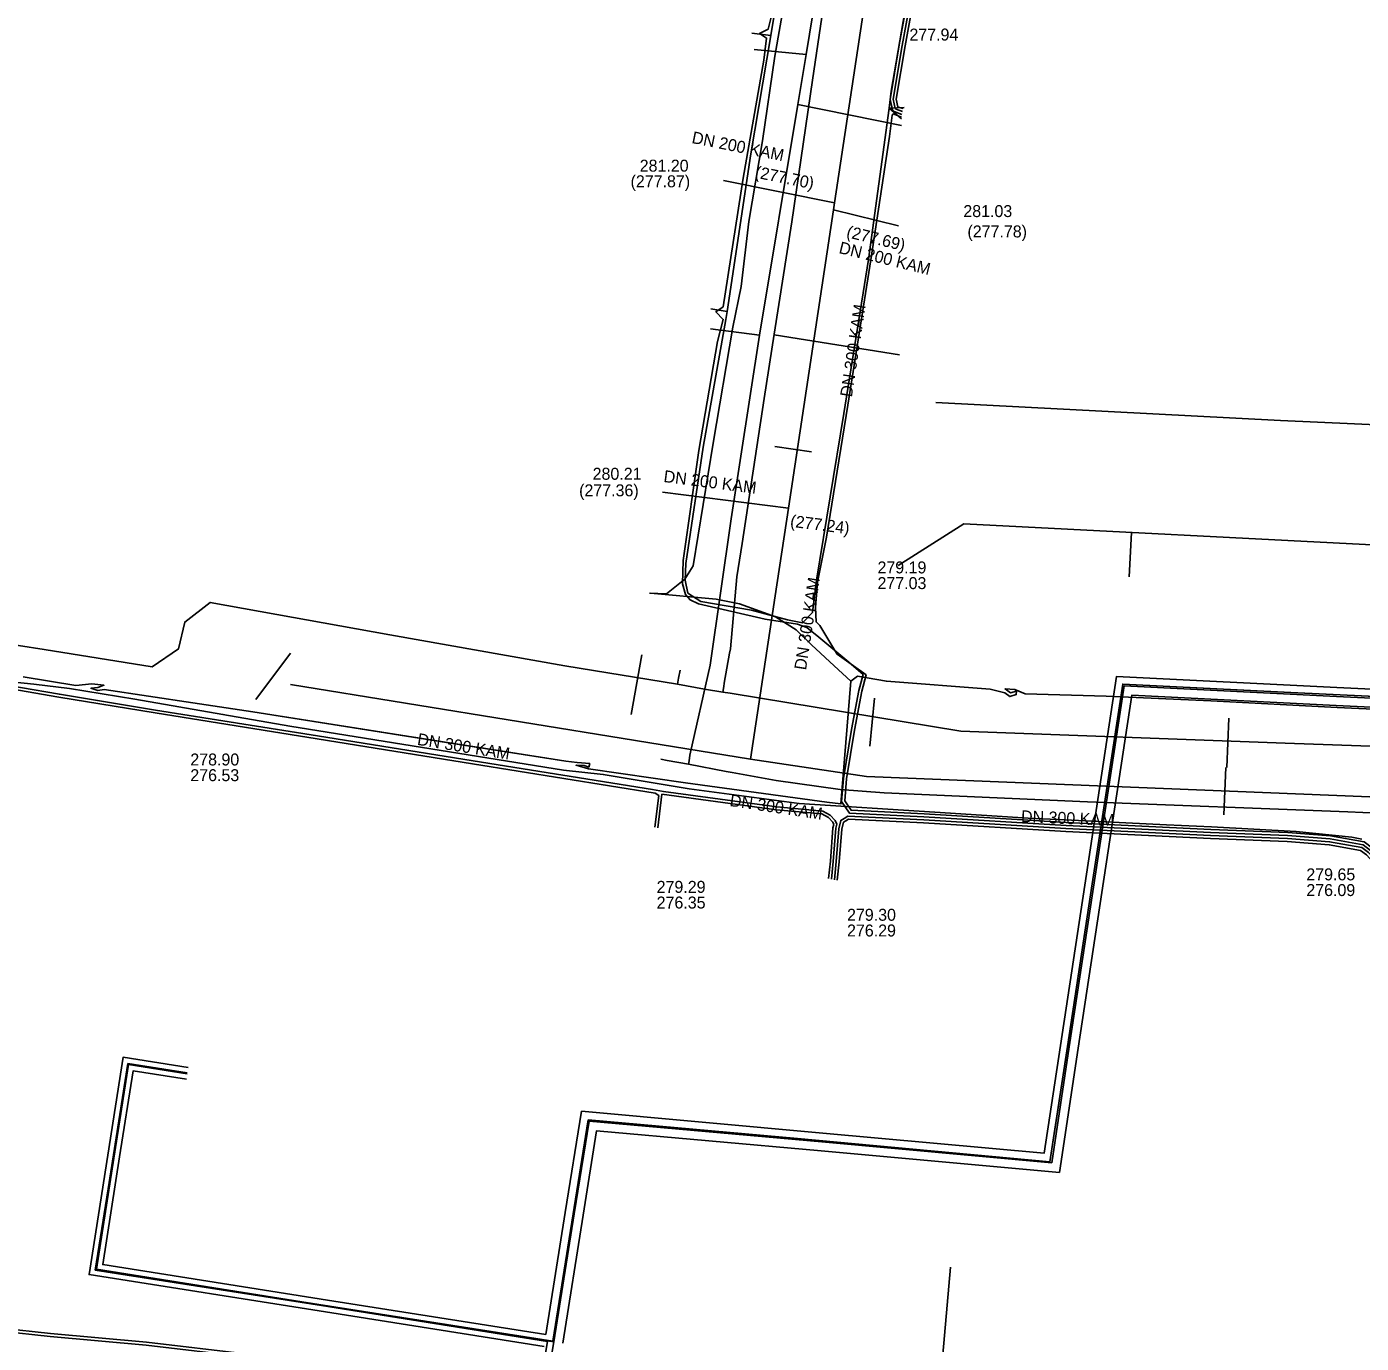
# Model space of a CAD drawing. Extents: x -598233 to -596890, y -1157848 to -1156431.
# Drawn here: x -597957.3 to -597868, y -1156848.3 to -1156760.2 of the extents above; entities that cross this region are included whole.
import ezdxf

# ---------------------------------------------------------------- set-up
doc = ezdxf.new("R2010")
doc.units = 0
for name, color, linetype in [('Vrstva 1', 7, 'Continuous'), ('Vrstva 13', 7, 'Continuous'), ('Vrstva 19', 7, 'Continuous'), ('Vrstva 25', 7, 'Continuous'), ('Vrstva 26', 7, 'Continuous'), ('Vrstva 37', 7, 'Continuous'), ('Vrstva 42', 7, 'Continuous'), ('Vrstva 44', 7, 'Continuous'), ('Vrstva 5', 7, 'Continuous'), ('Vrstva 55', 7, 'Continuous'), ('Vrstva 58', 7, 'Continuous'), ('Vrstva 8', 7, 'Continuous')]:
    doc.layers.add(name, color=color, linetype=linetype)

msp = doc.modelspace()

# ---------------------------------------------------------------- linework, layer by layer
at = {"layer": 'Vrstva 1'}
for p, q in [((-597899.02, -1156796.29), (-597894.63, -1156793.51)), ((-597894.63, -1156793.51), (-597864.35, -1156795.06)), ((-597883.57, -1156797.04), (-597883.419, -1156794.084)), ((-597895.53, -1156843.24), (-597897.05, -1156861.04))]:
    msp.add_line(p, q, dxfattribs=at)
for points in [[(-597904.83, -1156788.69), (-597907.277, -1156788.327)], [(-597941.99, -1156805.25), (-597939.685, -1156802.163)], [(-597916.17, -1156802.26), (-597916.89, -1156806.26)], [(-597900.601, -1156805.16), (-597900.92, -1156808.372)], [(-597876.89, -1156806.5), (-597877.039, -1156809.8)], [(-597877.24, -1156812.97), (-597877.096, -1156809.797)]]:
    msp.add_lwpolyline(points, dxfattribs=at)
at = {"layer": 'Vrstva 13'}
for p, q in [((-597898.93, -1156782.18), (-597907.31, -1156780.854)), ((-597910.299, -1156802.151), (-597910.654, -1156804.16)), ((-597910.695, -1156804.398), (-597910.76, -1156804.76)), ((-597910.654, -1156804.16), (-597910.695, -1156804.398)), ((-597910.254, -1156804.837), (-597910.76, -1156804.76))]:
    msp.add_line(p, q, dxfattribs=at)
for points in [[(-597903.77, -1156757.16), (-597904.752, -1156763.799), (-597906.14, -1156773.28), (-597907.31, -1156780.815), (-597907.98, -1156785.12), (-597909.466, -1156794.817), (-597909.81, -1156797.04), (-597910.25, -1156801.87), (-597910.299, -1156802.151)], [(-597910.76, -1156804.76), (-597911.98, -1156804.56), (-597913.78, -1156804.24), (-597921.32, -1156803), (-597933.03, -1156800.94), (-597945.05, -1156798.76), (-597946.76, -1156800.08), (-597947.18, -1156801.87), (-597948.94, -1156803.06), (-597956.16, -1156801.92), (-597959.63, -1156801.37), (-597971.35, -1156799.42), (-597983.27, -1156797.49), (-597988.23, -1156797.53), (-597994.44, -1156797.61), (-597996.35, -1156798.12), (-598005.74, -1156805.9), (-598006.045, -1156806.165), (-598006.36, -1156806.44), (-598007.14, -1156807.32), (-598007.96, -1156807.428)], [(-597913.78, -1156804.24), (-597913.709, -1156803.833), (-597913.612, -1156803.3)], [(-597795.967, -1156816.025), (-597812.956, -1156812.495), (-597815.93, -1156811.88), (-597823.17, -1156810.33), (-597823.982, -1156810.292), (-597843.08, -1156809.41), (-597849.715, -1156809.134), (-597866.8, -1156808.41), (-597873.134, -1156808.177), (-597894.82, -1156807.38), (-597910.254, -1156804.837)]]:
    msp.add_lwpolyline(points, dxfattribs=at)
at = {"layer": 'Vrstva 19'}
for points in [[(-597903.62, -1156752.54), (-597905.17, -1156762.1), (-597905.73, -1156765.43), (-597908.29, -1156780.88), (-597910.2, -1156793.17), (-597911.6, -1156802.97)], [(-597905.17, -1156762.1), (-597908.66, -1156761.76)], [(-597905.73, -1156765.43), (-597898.79, -1156766.85)], [(-597908.29, -1156780.88), (-597911.57, -1156780.44)], [(-597913.04, -1156809.59), (-597913.014, -1156809.37), (-597912.97, -1156808.99), (-597911.6, -1156802.97)], [(-597801.34, -1156819.11), (-597804.12, -1156818.41), (-597805.138, -1156818.257), (-597807.137, -1156817.956), (-597808.811, -1156817.705), (-597810.24, -1156817.49), (-597815.41, -1156816.67), (-597823.52, -1156815.24), (-597826.48, -1156814.85), (-597831.59, -1156814.44), (-597847.65, -1156813.6), (-597865.92, -1156812.91), (-597868.94, -1156812.78), (-597886.35, -1156812.11), (-597899.95, -1156811.51), (-597902.9, -1156811.28), (-597907.18, -1156810.68), (-597910.13, -1156810.14), (-597910.52, -1156810.07), (-597913.04, -1156809.59), (-597914.47, -1156809.33), (-597914.91, -1156809.25)]]:
    msp.add_lwpolyline(points, dxfattribs=at)
at = {"layer": 'Vrstva 25'}
msp.add_line((-597922.054, -1156848.246), (-597923.119, -1156854.422), dxfattribs=at)
for points in [[(-597836.113, -1156806.847), (-597849.17, -1156806.043), (-597869.696, -1156805.05), (-597883.904, -1156804.353), (-597887.574, -1156828.509)], [(-597887.574, -1156828.509), (-597888.74, -1156836.263), (-597904.123, -1156834.866), (-597919.701, -1156833.466), (-597920.699, -1156839.674), (-597922.054, -1156848.246)], [(-597922.054, -1156848.246), (-597937.275, -1156845.851), (-597952.704, -1156843.413), (-597951.518, -1156835.809), (-597950.538, -1156829.648), (-597946.587, -1156830.278)]]:
    msp.add_lwpolyline(points, dxfattribs=at)
at = {"layer": 'Vrstva 26'}
for points in [[(-597888.167, -1156828.419), (-597884.416, -1156803.727), (-597869.666, -1156804.45), (-597849.137, -1156805.444), (-597836.66, -1156806.213)], [(-597836.15, -1156807.446), (-597849.203, -1156806.642), (-597869.725, -1156805.649), (-597883.393, -1156804.978), (-597886.98, -1156828.599)], [(-597922.585, -1156847.758), (-597921.292, -1156839.579), (-597920.204, -1156832.818), (-597904.069, -1156834.269), (-597889.249, -1156835.614), (-597888.167, -1156828.42)], [(-597922.715, -1156848.547), (-597937.337, -1156846.246), (-597953.161, -1156843.746), (-597951.913, -1156835.747), (-597950.87, -1156829.191), (-597946.524, -1156829.883)], [(-597886.98, -1156828.599), (-597888.231, -1156836.912), (-597904.177, -1156835.464), (-597919.197, -1156834.114), (-597920.107, -1156839.768), (-597921.462, -1156848.34)], [(-597946.65, -1156830.673), (-597950.206, -1156830.106), (-597951.123, -1156835.871), (-597952.247, -1156843.08), (-597937.212, -1156845.456), (-597922.585, -1156847.758)]]:
    msp.add_lwpolyline(points, dxfattribs=at)
at = {"layer": 'Vrstva 37'}
for points in [[(-597834.656, -1156791.321), (-597835.862, -1156803.035), (-597836.208, -1156806.736), (-597848.804, -1156805.961), (-597857.619, -1156805.511), (-597872.759, -1156804.783), (-597883.997, -1156804.232), (-597886.045, -1156817.593), (-597887.688, -1156828.492)], [(-597887.688, -1156828.492), (-597888.882, -1156836.2), (-597905.766, -1156834.644), (-597919.763, -1156833.394), (-597922.133, -1156848.2), (-597938.927, -1156845.557), (-597952.665, -1156843.389), (-597951.391, -1156835.249), (-597950.51, -1156829.692), (-597946.596, -1156830.31)], [(-597946.602, -1156830.25), (-597950.563, -1156829.619), (-597951.712, -1156836.877), (-597952.736, -1156843.436), (-597937.615, -1156845.824), (-597922.483, -1156848.221), (-597923.518, -1156854.323)]]:
    msp.add_lwpolyline(points, dxfattribs=at)
at = {"layer": 'Vrstva 42'}
for points in [[(-597898.774, -1156766.104), (-597899.289, -1156765.906), (-597899.404, -1156765.804), (-597899.553, -1156765.095), (-597898.957, -1156761.446), (-597897.685, -1156754.523)], [(-597897.49, -1156754.57), (-597898.76, -1156761.48), (-597899.35, -1156765.09), (-597899.222, -1156765.698), (-597899.156, -1156765.756), (-597898.724, -1156765.909)], [(-597897.295, -1156754.617), (-597898.563, -1156761.514), (-597899.147, -1156765.085), (-597899.04, -1156765.592), (-597899.024, -1156765.606), (-597898.694, -1156765.708)], [(-597902.45, -1156802.64), (-597903.259, -1156801.97), (-597904.32, -1156801.09), (-597905.14, -1156800.43), (-597905.76, -1156800.22), (-597907.93, -1156799.89), (-597912.39, -1156798.85), (-597912.94, -1156798.59), (-597913.26, -1156798.24), (-597913.45, -1156797.52), (-597913.41, -1156795.96), (-597912.37, -1156788.6), (-597911.11, -1156781.29), (-597910.72, -1156779.82), (-597911.22, -1156779.31), (-597910.74, -1156778.97), (-597909.39, -1156770.36), (-597908.01, -1156762.47), (-597907.83, -1156760.99), (-597908.3, -1156760.69), (-597907.72, -1156760.4), (-597907.24, -1156758.41)], [(-597904.27, -1156800.31), (-597904.51, -1156800.07), (-597904.55, -1156799.1), (-597904.41, -1156797.4), (-597903.81, -1156794.39), (-597902.38, -1156785.57), (-597900.85, -1156775.83), (-597899.6, -1156767.59), (-597899.42, -1156766.15), (-597899.352, -1156766.062), (-597898.792, -1156766.277)], [(-597834.66, -1156791.32), (-597835.86, -1156803.04), (-597836.21, -1156806.74), (-597848.8, -1156805.96), (-597857.62, -1156805.51), (-597872.76, -1156804.78), (-597884, -1156804.23), (-597886.05, -1156817.59), (-597887.69, -1156828.49)], [(-597904.27, -1156800.31), (-597903.259, -1156801.97), (-597903.1, -1156802.23), (-597902.173, -1156802.884), (-597901.164, -1156803.596), (-597901.462, -1156804.692), (-597901.941, -1156807.307), (-597902.471, -1156810.572), (-597902.597, -1156812.034), (-597902.174, -1156812.665), (-597897.283, -1156812.92), (-597887.774, -1156813.5), (-597878.107, -1156813.96), (-597872.953, -1156814.16), (-597870.102, -1156814.382), (-597867.837, -1156814.787), (-597867.277, -1156815.207), (-597864.79, -1156817.956), (-597863.296, -1156819.535), (-597855.354, -1156819.871), (-597852.938, -1156820.162), (-597852.423, -1156820.58), (-597852.521, -1156821.826)], [(-597852.72, -1156821.81), (-597852.63, -1156820.669), (-597853.019, -1156820.354), (-597855.386, -1156820.07), (-597863.385, -1156819.732), (-597864.937, -1156818.092), (-597867.412, -1156815.356), (-597867.919, -1156814.976), (-597870.127, -1156814.581), (-597872.964, -1156814.36), (-597878.116, -1156814.16), (-597887.785, -1156813.7), (-597897.294, -1156813.12), (-597902.284, -1156812.86), (-597902.803, -1156812.086), (-597902.669, -1156810.548), (-597902.139, -1156807.273), (-597901.658, -1156804.648), (-597901.37, -1156803.592), (-597902.173, -1156802.884), (-597902.45, -1156802.64)], [(-597961.001, -1156807.945), (-597960.581, -1156804.703), (-597960.57, -1156804.29), (-597960.473, -1156804.187), (-597955.177, -1156805.109), (-597948.746, -1156806.159), (-597937.906, -1156807.879), (-597927.496, -1156809.559), (-597915.279, -1156811.522), (-597915.043, -1156811.686), (-597915.309, -1156813.804)], [(-597960.373, -1156804.001), (-597955.143, -1156804.911), (-597948.714, -1156805.961), (-597937.874, -1156807.681), (-597927.464, -1156809.361), (-597915.454, -1156811.291), (-597914.716, -1156811.411), (-597907.149, -1156812.451), (-597904.07, -1156812.722), (-597903.568, -1156813), (-597903.236, -1156813.353), (-597903.122, -1156813.591), (-597903.189, -1156813.875), (-597903.36, -1156816.091), (-597903.489, -1156817.281)], [(-597915.111, -1156813.836), (-597914.83, -1156811.597), (-597907.171, -1156812.649), (-597904.13, -1156812.918), (-597903.692, -1156813.16), (-597903.403, -1156813.467), (-597903.333, -1156813.614), (-597903.387, -1156813.844), (-597903.559, -1156816.072), (-597903.686, -1156817.245)], [(-597903.291, -1156817.318), (-597903.16, -1156816.109), (-597902.991, -1156813.905), (-597902.859, -1156813.347), (-597902.633, -1156813.215), (-597902.394, -1156813.054), (-597897.306, -1156813.32), (-597887.795, -1156813.9), (-597878.124, -1156814.36), (-597872.976, -1156814.56), (-597870.153, -1156814.779), (-597868.001, -1156815.164), (-597867.548, -1156815.504), (-597865.083, -1156818.228), (-597863.475, -1156819.928), (-597855.402, -1156820.27), (-597853.101, -1156820.546), (-597852.838, -1156820.758), (-597852.919, -1156821.794)], [(-597903.094, -1156817.355), (-597902.961, -1156816.128), (-597902.793, -1156813.936), (-597902.685, -1156813.476), (-597902.527, -1156813.385), (-597902.338, -1156813.258), (-597897.317, -1156813.52), (-597887.806, -1156814.1), (-597878.133, -1156814.56), (-597872.987, -1156814.76), (-597870.178, -1156814.978), (-597868.083, -1156815.353), (-597867.683, -1156815.653), (-597865.23, -1156818.364), (-597863.564, -1156820.125), (-597855.403, -1156820.47), (-597853.182, -1156820.738), (-597853.046, -1156820.848), (-597853.119, -1156821.779)], [(-597887.69, -1156828.49), (-597888.88, -1156836.2), (-597905.77, -1156834.64), (-597919.76, -1156833.39), (-597922.13, -1156848.2), (-597938.93, -1156845.56), (-597952.67, -1156843.39), (-597951.39, -1156835.25), (-597950.51, -1156829.69), (-597946.6, -1156830.31)], [(-597946.6, -1156830.25), (-597950.56, -1156829.62), (-597951.71, -1156836.88), (-597952.74, -1156843.44), (-597937.61, -1156845.82), (-597922.48, -1156848.22), (-597923.52, -1156854.32)], [(-597962.342, -1156847.169), (-597955.76, -1156847.89), (-597949.33, -1156848.469), (-597942.54, -1156849.279), (-597940.808, -1156849.436), (-597940.122, -1156850.208), (-597938.524, -1156853.115), (-597936.304, -1156855.962), (-597936.131, -1156856.946), (-597936.5, -1156863.093), (-597936.673, -1156865.248), (-597936.427, -1156865.599), (-597933.734, -1156865.861), (-597932.464, -1156866.15), (-597931.628, -1156867.202), (-597931.392, -1156867.911)], [(-597962.318, -1156846.971), (-597955.74, -1156847.69), (-597949.31, -1156848.271), (-597942.52, -1156849.081)]]:
    msp.add_lwpolyline(points, dxfattribs=at)
at = {"layer": 'Vrstva 44'}
msp.add_lwpolyline([(-597867.99, -1156814.61), (-597868.67, -1156814.46), (-597872.4, -1156814.1), (-597878.05, -1156813.78), (-597881.07, -1156813.65), (-597887.86, -1156813.3), (-597890.33, -1156813.19), (-597896.57, -1156812.79), (-597905.64, -1156812.21), (-597913.01, -1156811.23), (-597918.75, -1156810.27), (-597921.42, -1156809.98), (-597929.04, -1156808.75), (-597939.73, -1156807.04), (-597944.2, -1156806.25), (-597950.09, -1156805.24), (-597954.46, -1156804.53), (-597956.85, -1156804.23), (-597961.87, -1156803.72)], dxfattribs=at)
at = {"layer": 'Vrstva 5'}
for p, q in [((-597910.71, -1156770.53), (-597903.281, -1156772.019)), ((-597910.71, -1156770.53), (-597903.281, -1156772.019)), ((-597899, -1156773.56), (-597903.353, -1156772.494)), ((-597899, -1156773.56), (-597903.353, -1156772.494)), ((-597914.79, -1156791.38), (-597906.365, -1156792.458)), ((-597914.79, -1156791.38), (-597906.365, -1156792.458)), ((-597907.25, -1156798.32), (-597908.91, -1156809.24)), ((-597939.69, -1156804.25), (-597908.91, -1156809.24)), ((-597908.91, -1156809.24), (-597901.13, -1156810.41)), ((-597901.13, -1156810.41), (-597867.46, -1156811.77))]:
    msp.add_line(p, q, dxfattribs=at)
msp.add_lwpolyline([(-597901.14, -1156757.83), (-597903.281, -1156772.019), (-597903.353, -1156772.494), (-597906.365, -1156792.458), (-597907.25, -1156798.32)], dxfattribs=at)
at = {"layer": 'Vrstva 55'}
for p, q in [((-597896.51, -1156785.39), (-597873.44, -1156786.58)), ((-597873.44, -1156786.58), (-597865.931, -1156786.932))]:
    msp.add_line(p, q, dxfattribs=at)
for points in [[(-597906.13, -1156755.71), (-597907.28, -1156762.21), (-597908.09, -1156767.87), (-597909.01, -1156773.27), (-597909.52, -1156777.62), (-597910.08, -1156780.35), (-597911.41, -1156788.1), (-597912.74, -1156796.31), (-597913.3, -1156797.2), (-597914.52, -1156798.18), (-597915.659, -1156798.134)], [(-597957.572, -1156803.746), (-597954.04, -1156804.31), (-597952.98, -1156804.21), (-597952.17, -1156804.3), (-597952.58, -1156804.46), (-597953.04, -1156804.5), (-597952.57, -1156804.66), (-597952.15, -1156804.59), (-597946.207, -1156805.485), (-597942.19, -1156806.09), (-597928.827, -1156808.196), (-597921.25, -1156809.39), (-597920.49, -1156809.47), (-597919.66, -1156809.54), (-597919.72, -1156809.78), (-597920.03, -1156809.68), (-597920.57, -1156809.66), (-597919.74, -1156809.9), (-597913.26, -1156810.83), (-597903.796, -1156812.121), (-597902.85, -1156812.25), (-597902.18, -1156804.04), (-597903.3, -1156803), (-597904.82, -1156801.6), (-597905.85, -1156800.6), (-597907.24, -1156799.72), (-597909.64, -1156798.86), (-597911.19, -1156798.55), (-597915.6, -1156798.135)], [(-597915.6, -1156798.135), (-597911.19, -1156798.55), (-597909.64, -1156798.86), (-597907.24, -1156799.72), (-597905.85, -1156800.6), (-597904.82, -1156801.6), (-597903.3, -1156803), (-597902.18, -1156804.04), (-597901.75, -1156803.7), (-597899.81, -1156804.04), (-597892.87, -1156804.56), (-597891.88, -1156804.8), (-597891.55, -1156805.06), (-597891.12, -1156804.93), (-597891.11, -1156804.71), (-597891.51, -1156804.82), (-597891.87, -1156804.55), (-597891.21, -1156804.59), (-597890.53, -1156804.87), (-597885.1, -1156805.03), (-597878.11, -1156805.35), (-597869.65, -1156805.8), (-597862.37, -1156806.13)], [(-597957.572, -1156803.746), (-597954.04, -1156804.31), (-597952.98, -1156804.21), (-597952.17, -1156804.3), (-597952.58, -1156804.46), (-597953.04, -1156804.5), (-597952.57, -1156804.66), (-597952.15, -1156804.59), (-597946.207, -1156805.485), (-597942.19, -1156806.09), (-597921.25, -1156809.39), (-597920.49, -1156809.47), (-597919.66, -1156809.54), (-597919.72, -1156809.78), (-597920.03, -1156809.68), (-597920.57, -1156809.66), (-597919.74, -1156809.9), (-597913.26, -1156810.83), (-597903.796, -1156812.121), (-597902.85, -1156812.25), (-597902.18, -1156804.04), (-597901.75, -1156803.7), (-597899.81, -1156804.04), (-597892.87, -1156804.56), (-597891.88, -1156804.8), (-597891.55, -1156805.06), (-597891.12, -1156804.93), (-597891.11, -1156804.71), (-597891.51, -1156804.82), (-597891.87, -1156804.55), (-597891.21, -1156804.59), (-597890.53, -1156804.87), (-597885.1, -1156805.03), (-597878.11, -1156805.35), (-597869.65, -1156805.8), (-597862.37, -1156806.13)], [(-597957.572, -1156803.746), (-597954.04, -1156804.31), (-597952.98, -1156804.21), (-597952.17, -1156804.3), (-597952.58, -1156804.46), (-597953.04, -1156804.5), (-597952.57, -1156804.66), (-597952.15, -1156804.59), (-597946.207, -1156805.485), (-597942.19, -1156806.09), (-597921.25, -1156809.39), (-597920.49, -1156809.47), (-597919.66, -1156809.54), (-597919.72, -1156809.78), (-597920.03, -1156809.68), (-597920.57, -1156809.66), (-597919.74, -1156809.9), (-597913.26, -1156810.83), (-597903.796, -1156812.121), (-597902.85, -1156812.25), (-597902.18, -1156804.04), (-597901.75, -1156803.7), (-597899.81, -1156804.04), (-597892.87, -1156804.56), (-597891.88, -1156804.8), (-597891.55, -1156805.06), (-597891.12, -1156804.93), (-597891.11, -1156804.71), (-597891.51, -1156804.82), (-597891.87, -1156804.55), (-597891.21, -1156804.59), (-597890.53, -1156804.87), (-597885.1, -1156805.03), (-597878.11, -1156805.35), (-597869.65, -1156805.8), (-597862.37, -1156806.13)]]:
    msp.add_lwpolyline(points, dxfattribs=at)
at = {"layer": 'Vrstva 58'}
for p, q in [((-597907.55, -1156760.83), (-597908.82, -1156760.66)), ((-597899.63, -1156765.69), (-597898.62, -1156765.64)), ((-597899.63, -1156765.69), (-597898.79, -1156766.4)), ((-597910.46, -1156779.28), (-597911.56, -1156779.12))]:
    msp.add_line(p, q, dxfattribs=at)
for points in [[(-597899.63, -1156765.69), (-597899.49, -1156764.54), (-597897.78, -1156754.56), (-597895.99, -1156748.04), (-597895.1, -1156746.08), (-597892.99, -1156742.32), (-597891.23, -1156739.46), (-597887.84, -1156735.15), (-597881.5, -1156728.65), (-597876.88, -1156724.22), (-597868.22, -1156715.83)], [(-597904.38, -1156747.11), (-597904.71, -1156747.97), (-597905.98, -1156752.18), (-597906.67, -1156755.55), (-597907.55, -1156760.83)], [(-597907.55, -1156760.83), (-597908.88, -1156768.75), (-597910.46, -1156779.28)], [(-597904.75, -1156799.43), (-597904.49, -1156797.28), (-597902.66, -1156786.11), (-597901.01, -1156775.81), (-597899.63, -1156765.69)], [(-597910.46, -1156779.28), (-597910.55, -1156779.83), (-597912.07, -1156788.36), (-597913.23, -1156796.15), (-597913.28, -1156797.26), (-597913.09, -1156798.13), (-597912.23, -1156798.7), (-597908.84, -1156799.28), (-597906.43, -1156799.93), (-597905.43, -1156800.13), (-597904.75, -1156799.43)]]:
    msp.add_lwpolyline(points, dxfattribs=at)

# ---------------------------------------------------------------- texts
at = {"layer": 'Vrstva 8'}
for s, p in [('277.94', (-597898.268, -1156761.158)), ('281.20', (-597916.315, -1156769.931)), ('(277.87)', (-597916.926, -1156770.976)), ('281.03', (-597894.661, -1156772.971)), ('(277.78)', (-597894.387, -1156774.333)), ('280.21', (-597919.465, -1156790.55)), ('(277.36)', (-597920.369, -1156791.66)), ('279.19', (-597900.405, -1156796.818)), ('277.03', (-597900.405, -1156797.868)), ('278.90', (-597946.383, -1156809.672)), ('276.53', (-597946.383, -1156810.722)), ('279.65', (-597871.71, -1156817.361)), ('279.29', (-597915.181, -1156818.196)), ('276.09', (-597871.71, -1156818.411)), ('276.35', (-597915.181, -1156819.246)), ('279.30', (-597902.442, -1156820.066)), ('276.29', (-597902.442, -1156821.116))]:
    msp.add_text(s, height=0.8, dxfattribs=at).set_placement(p)
for s, rotation, p in [('DN 200 KAM', 348.66342, (-597912.874, -1156768.01)), ('(277.70)', 348.66342, (-597908.649, -1156770.324)), ('(277.69)', 346.23893, (-597902.529, -1156774.309)), ('DN 200 KAM', 346.23893, (-597903.038, -1156775.372)), ('DN 300 KAM', 81.41873, (-597902.12, -1156785.055)), ('DN 200 KAM', 352.70841, (-597914.749, -1156790.697)), ('(277.24)', 352.69081, (-597906.278, -1156793.69)), ('DN 300 KAM', 81.35638, (-597905.188, -1156803.323)), ('DN 300 KAM', 350.79142, (-597931.238, -1156808.289)), ('DN 300 KAM', 351.44763, (-597910.327, -1156812.381)), ('DN 300 KAM', 357.68696, (-597890.813, -1156813.47))]:
    msp.add_text(s, height=0.8, rotation=rotation, dxfattribs=at).set_placement(p)

doc.saveas('drawing.dxf')
